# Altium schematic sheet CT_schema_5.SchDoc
size 229 x 185 mm
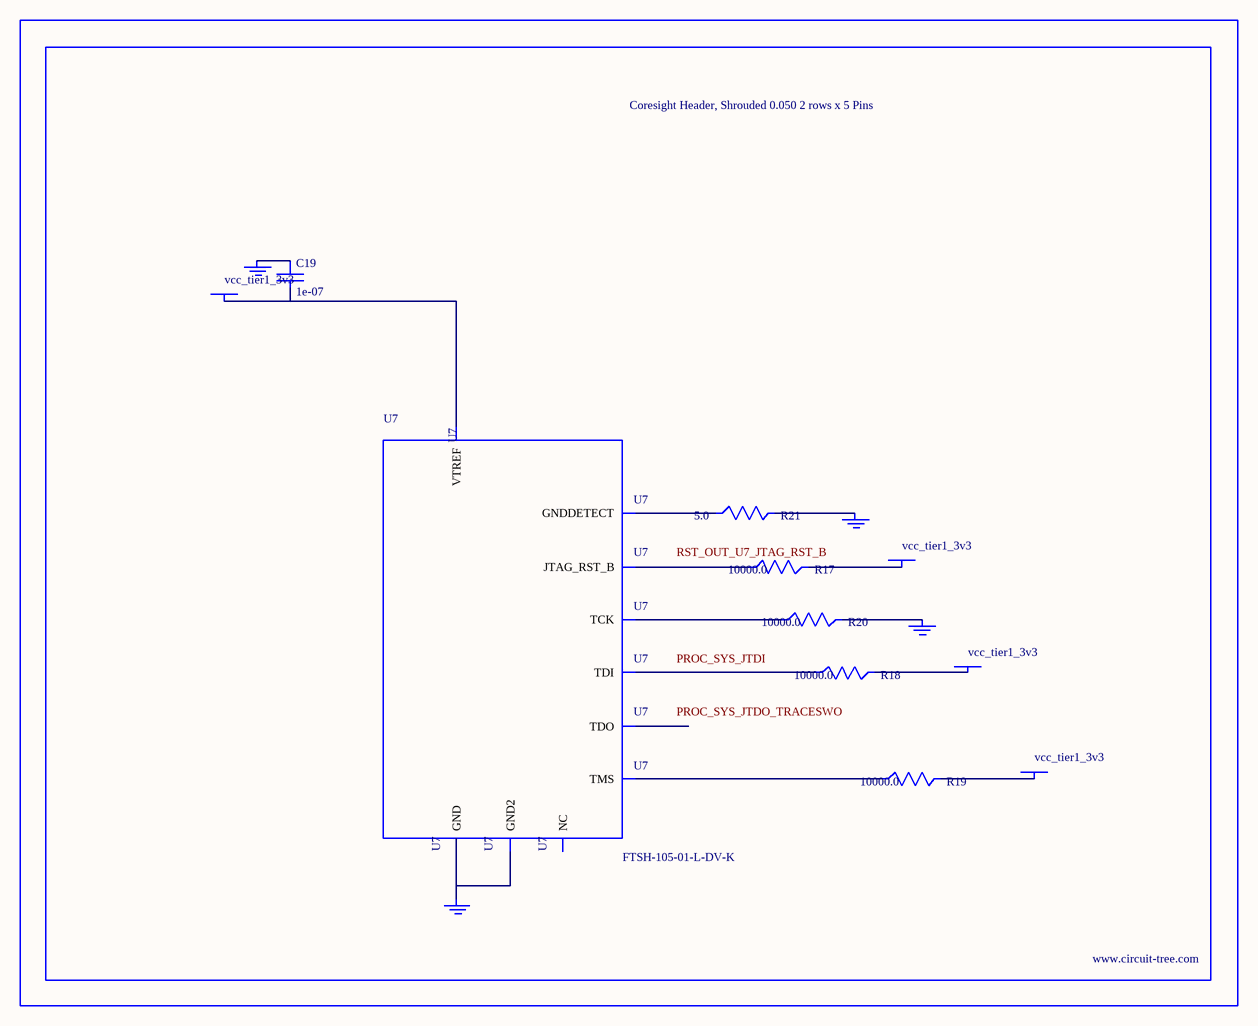
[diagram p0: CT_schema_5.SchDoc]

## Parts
BORDER4  (no value)
C19  1e-07  [C0402]
GND_INSTANCE_4_0  (no value)
GND_INSTANCE_4_1  (no value)
GND_INSTANCE_4_2  (no value)
GND_INSTANCE_4_3  (no value)
POWER_INSTANCE_4_0  vcc_tier1_3v3
POWER_INSTANCE_4_1  vcc_tier1_3v3
POWER_INSTANCE_4_2  vcc_tier1_3v3
POWER_INSTANCE_4_3  vcc_tier1_3v3
R17  10000.0  [R0603]
R18  10000.0  [R0603]
R19  10000.0  [R0603]
R20  10000.0  [R0603]
R21  5.0  [R0603]
U7  FTSH-105-01-L-DV-K  [SAMTEC_FTSH-105-01-L-DV-K]

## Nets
NetC19_1: C19.1 GND_INSTANCE_4_0.0(GND)
NetC19_2: C19.2 POWER_INSTANCE_4_0.0(PWR) U7.1(VTREF)
NetGND_INSTANCE_4_1_0: GND_INSTANCE_4_1.0(GND) R20.2
NetGND_INSTANCE_4_2_0: GND_INSTANCE_4_2.0(GND) R21.2
NetGND_INSTANCE_4_3_0: GND_INSTANCE_4_3.0(GND) U7.3(GND) U7.5(GND2)
NetPOWER_INSTANCE_4_1_0: POWER_INSTANCE_4_1.0(PWR) R19.2
NetPOWER_INSTANCE_4_2_0: POWER_INSTANCE_4_2.0(PWR) R18.2
NetPOWER_INSTANCE_4_3_0: POWER_INSTANCE_4_3.0(PWR) R17.2
NetR17_1: R17.1 U7.10(JTAG_RST_B)
NetR18_1: R18.1 U7.8(TDI)
NetR19_1: R19.1 U7.2(TMS)
NetR20_1: R20.1 U7.4(TCK)
NetR21_1: R21.1 U7.9(GNDDETECT)

Not connected (* = marked no-connect by the designer): U7 6(TDO) 7(NC)

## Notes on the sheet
- Labels drawn without touching a wire or pin: PROC_SYS_JTDI, PROC_SYS_JTDO_TRACESWO, RST_OUT_U7_JTAG_RST_B

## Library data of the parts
BORDER4 = BORDER_PAGE4
C19 = C0402C104K3RACTU
GND_INSTANCE_4_0-GND_INSTANCE_4_3 = GND
POWER_INSTANCE_4_0-POWER_INSTANCE_4_3 = PWR
R17-R20 = RC0603JR-0710KL
R21 = ERJ-3GEYJ5R1V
